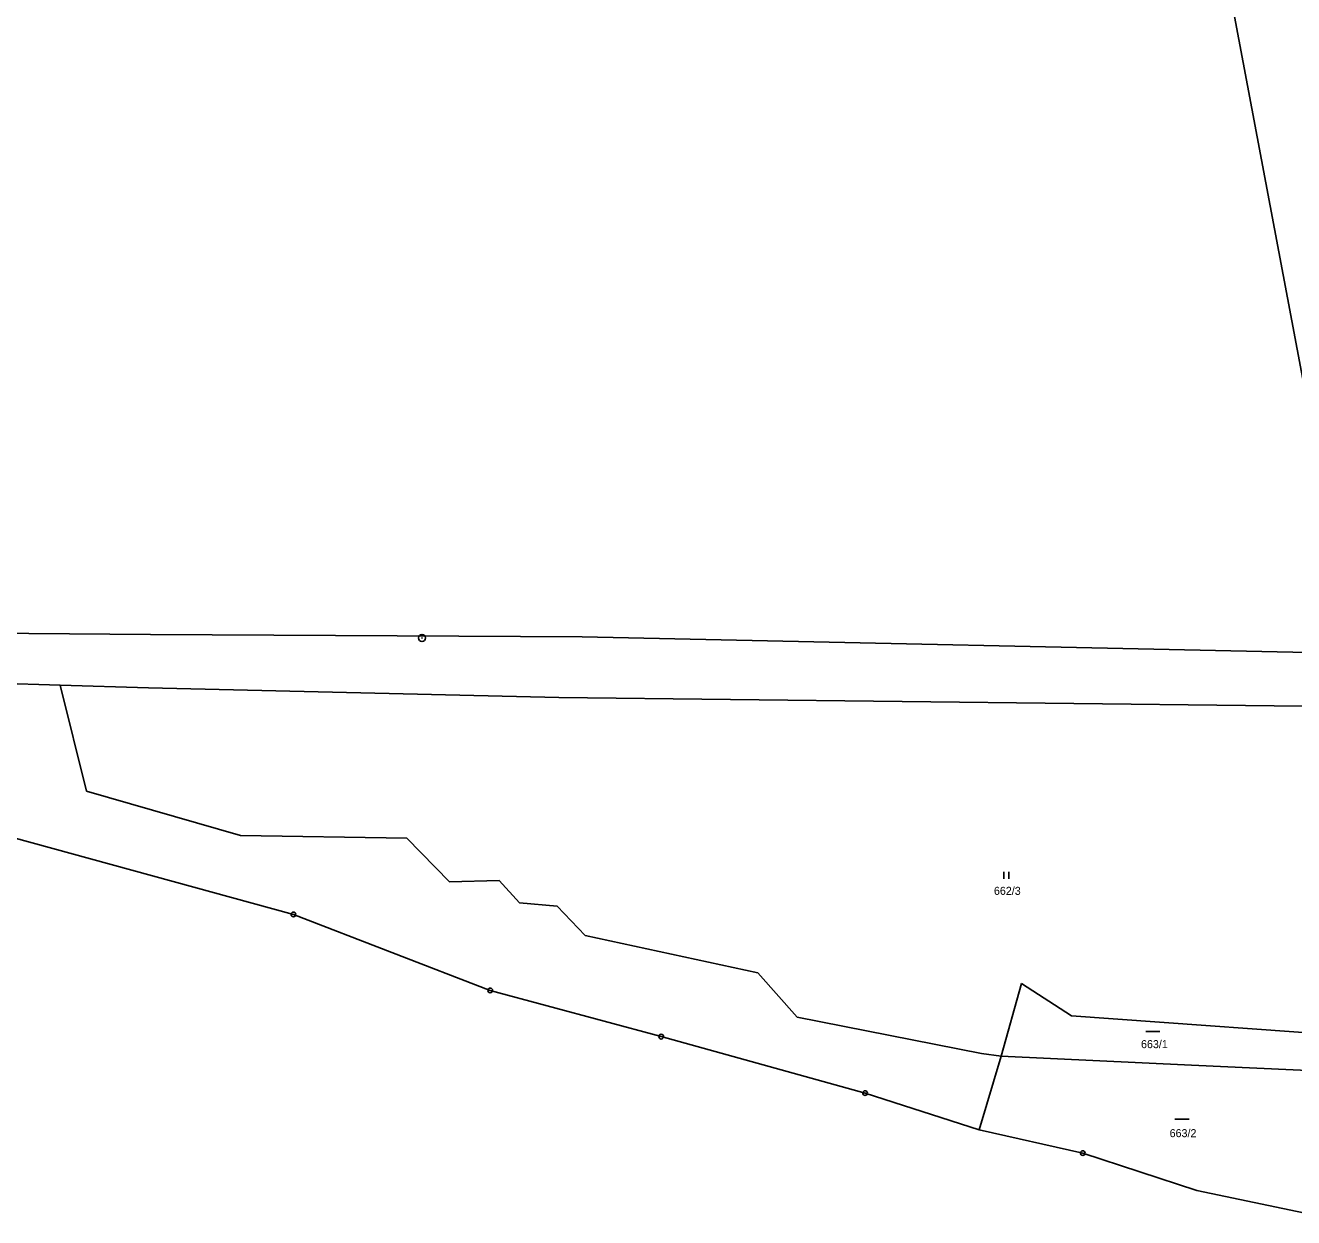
# Model space of a CAD drawing. Extents: x -779596 to -776743, y -1030330 to -1024513.
# Drawn here: x -778344 to -778074.5, y -1028522.4 to -1028269.2 of the extents above; entities that cross this region are included whole.
import ezdxf

# ---------------------------------------------------------------- set-up
doc = ezdxf.new("R2010")
doc.units = 0
for name, color, linetype in [('hranice parcel', 7, 'Continuous'), ('kultura', 7, 'Continuous'), ('Kód', 7, 'Continuous'), ('č_parcel poz_', 7, 'Continuous')]:
    doc.layers.add(name, color=color, linetype=linetype)

msp = doc.modelspace()

# ---------------------------------------------------------------- linework, layer by layer
at = {"layer": 'hranice parcel'}
for points in [[(-778145.62, -1027956.41), (-778061.55, -1028402.58)], [(-778377.73, -1028398.08), (-778317.39, -1028398.61)], [(-778317.39, -1028398.61), (-778225.68, -1028399.1)], [(-778225.68, -1028399.1), (-778061.55, -1028402.58)], [(-778336.57, -1028409.34), (-778377.67, -1028408.04)], [(-778317.77, -1028409.93), (-778336.57, -1028409.34)], [(-778330.96, -1028431.83), (-778336.57, -1028409.34)], [(-778230.65, -1028411.96), (-778317.77, -1028409.93)], [(-778011.79, -1028414.49), (-778230.65, -1028411.96)], [(-778298.23, -1028441.3), (-778330.96, -1028431.83)], [(-778287.01, -1028458.05), (-778351.35, -1028440.39)], [(-778262.9, -1028441.86), (-778298.23, -1028441.3)], [(-778253.88, -1028451.14), (-778262.9, -1028441.86)], [(-778243.28, -1028450.83), (-778253.88, -1028451.14)], [(-778239.01, -1028455.58), (-778243.28, -1028450.83)], [(-778231, -1028456.26), (-778239.01, -1028455.58)], [(-778245.2, -1028474.19), (-778287.01, -1028458.05)], [(-778225.06, -1028462.49), (-778231, -1028456.26)], [(-778188.35, -1028470.44), (-778225.06, -1028462.49)], [(-778179.97, -1028479.89), (-778188.35, -1028470.44)], [(-778208.87, -1028484), (-778245.2, -1028474.19)], [(-778132.34, -1028472.74), (-778136.68, -1028488.13)], [(-778121.72, -1028479.59), (-778132.34, -1028472.74)], [(-778140.83, -1028487.55), (-778179.97, -1028479.89)], [(-778054.75, -1028484.4), (-778121.72, -1028479.59)], [(-778165.57, -1028495.98), (-778208.87, -1028484)], [(-778136.68, -1028488.13), (-778141.3, -1028503.77)], [(-778136.68, -1028488.13), (-778140.83, -1028487.55)], [(-778096.21, -1028490.06), (-778136.68, -1028488.13)], [(-778060.74, -1028491.71), (-778096.21, -1028490.06)], [(-778141.3, -1028503.77), (-778165.57, -1028495.98)], [(-778119.3, -1028508.73), (-778141.3, -1028503.77)], [(-778095.1, -1028516.66), (-778119.3, -1028508.73)], [(-778067.7, -1028522.44), (-778095.1, -1028516.66)]]:
    msp.add_lwpolyline(points, dxfattribs=at)
at = {"layer": 'kultura'}
for points in [[(-778136.077, -1028450.455), (-778136.077, -1028448.955)], [(-778135.043, -1028450.455), (-778135.043, -1028448.955)], [(-778105.94, -1028482.89), (-778102.94, -1028482.89)], [(-778099.73, -1028501.55), (-778096.73, -1028501.55)]]:
    msp.add_lwpolyline(points, dxfattribs=at)
at = {"layer": 'Kód'}
for centre, radius in [((-778259.69, -1028399.32), 0.75), ((-778259.69, -1028399.32), 0.032), ((-778287.01, -1028458.05), 0.5), ((-778287.01, -1028458.05), 0.032), ((-778245.2, -1028474.19), 0.5), ((-778245.2, -1028474.19), 0.032), ((-778208.87, -1028484), 0.5), ((-778208.87, -1028484), 0.032), ((-778165.57, -1028495.98), 0.5), ((-778165.57, -1028495.98), 0.032), ((-778119.3, -1028508.73), 0.5), ((-778119.3, -1028508.73), 0.032)]:
    msp.add_circle(centre, radius, dxfattribs=at)

# ---------------------------------------------------------------- texts
at = {"layer": 'č_parcel poz_'}
for s, p in [('662/3', (-778138.183, -1028453.88)), ('663/1', (-778106.933, -1028486.44)), ('663/2', (-778100.853, -1028505.35))]:
    msp.add_text(s, height=1.7, dxfattribs=at).set_placement(p)

doc.saveas('drawing.dxf')
